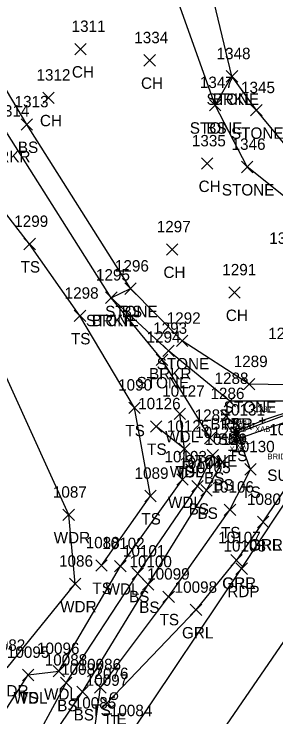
# Model space of a CAD drawing. Extents: x 1651685 to 1653558, y 889533 to 891085.
# Drawn here: x 1652635.2 to 1652681.1, y 890214.6 to 890337.8 of the extents above; entities that cross this region are included whole.
import ezdxf

# ---------------------------------------------------------------- set-up
doc = ezdxf.new("R2010")
doc.units = 0
for name, color, linetype in [('B_A', 7, 'Continuous'), ('B_C', 7, 'Continuous'), ('B_I', 7, 'Continuous'), ('B_TIC', 7, 'Continuous'), ('BSUBM', 7, 'Continuous'), ('C_A', 7, 'Continuous'), ('C_I', 7, 'Continuous'), ('CBP', 7, 'Continuous'), ('L_A', 7, 'Continuous'), ('L_I', 7, 'Continuous'), ('L_TIC', 7, 'Continuous'), ('LASF', 7, 'Continuous'), ('LAWA', 7, 'Continuous'), ('LAWE', 7, 'Continuous'), ('LELB', 7, 'Continuous'), ('P_A', 7, 'Continuous'), ('P_I', 7, 'Continuous'), ('P_TIC', 7, 'Continuous'), ('PET', 7, 'Continuous'), ('PRC', 7, 'Continuous'), ('R_A', 7, 'Continuous'), ('R_I', 7, 'Continuous'), ('R_TIC', 7, 'Continuous'), ('RGR', 7, 'Continuous'), ('U_A', 7, 'Continuous'), ('U_I', 7, 'Continuous')]:
    doc.layers.add(name, color=color, linetype=linetype)

msp = doc.modelspace()

# ---------------------------------------------------------------- linework, layer by layer
at = {"layer": 'B_TIC'}
for p, q in [((1652678.73, 890266.55), (1652678.8, 890266.55)), ((1652678.73, 890266.55), (1652678.8, 890266.55)), ((1652673.79, 890264.5), (1652673.87, 890264.5)), ((1652674.28, 890264.42), (1652674.36, 890264.42)), ((1652675.36, 890263.62), (1652675.43, 890263.62)), ((1652674.25, 890263.02), (1652674.33, 890263.02))]:
    msp.add_line(p, q, dxfattribs=at)
for points in [[(1652678.72, 890266.05), (1652678.72, 890267.05)], [(1652678.72, 890266.05), (1652678.72, 890267.05)], [(1652678.22, 890266.55), (1652679.22, 890266.55)], [(1652678.22, 890266.55), (1652679.22, 890266.55)], [(1652673.29, 890264.5), (1652674.29, 890264.5)], [(1652673.78, 890264.42), (1652674.78, 890264.42)], [(1652673.79, 890264), (1652673.79, 890265)], [(1652674.28, 890263.92), (1652674.28, 890264.92)], [(1652674.25, 890262.52), (1652674.25, 890263.52)], [(1652674.85, 890263.62), (1652675.85, 890263.62)], [(1652675.35, 890263.12), (1652675.35, 890264.12)], [(1652673.75, 890263.02), (1652674.75, 890263.02)]]:
    msp.add_lwpolyline(points, dxfattribs=at)
at = {"layer": 'BSUBM'}
for points in [[(1652674.28, 890264.42), (1652684.64, 890268.23), (1652686.91, 890265.29), (1652686.2, 890264.56), (1652684.09, 890266.74), (1652675.35, 890263.62)], [(1652707.27, 890221.55), (1652712.18, 890235.57), (1652700.43, 890249.63), (1652694.58, 890256.58), (1652684.61, 890268.45), (1652678.72, 890266.55)], [(1652674.25, 890263.02), (1652673.79, 890264.5), (1652678.72, 890266.55)]]:
    msp.add_lwpolyline(points, dxfattribs=at)
at = {"layer": 'CBP'}
for radius in [0.625, 0.0833]:
    msp.add_circle((1652652.72, 890218.25), radius, dxfattribs=at)
at = {"layer": 'L_TIC'}
for points in [[(1652645.86, 890330.63), (1652647.86, 890332.63)], [(1652647.86, 890330.63), (1652645.86, 890332.63)], [(1652657.97, 890328.65), (1652659.97, 890330.65)], [(1652659.97, 890328.65), (1652657.97, 890330.65)], [(1652672.4, 890325.85), (1652674.4, 890327.85)], [(1652674.4, 890325.85), (1652672.4, 890327.85)], [(1652672.4, 890325.85), (1652674.4, 890327.85)], [(1652674.4, 890325.85), (1652672.4, 890327.85)], [(1652672.4, 890325.85), (1652674.4, 890327.85)], [(1652674.4, 890325.85), (1652672.4, 890327.85)], [(1652640.26, 890322.1), (1652642.26, 890324.1)], [(1652642.26, 890322.1), (1652640.26, 890324.1)], [(1652669.46, 890320.8), (1652671.46, 890322.8)], [(1652671.46, 890320.8), (1652669.46, 890322.8)], [(1652669.46, 890320.8), (1652671.46, 890322.8)], [(1652671.46, 890320.8), (1652669.46, 890322.8)], [(1652676.67, 890319.9), (1652678.67, 890321.9)], [(1652678.67, 890319.9), (1652676.67, 890321.9)], [(1652636.44, 890317.42), (1652638.44, 890319.42)], [(1652638.44, 890317.42), (1652636.44, 890319.42)], [(1652668.06, 890310.58), (1652670.06, 890312.58)], [(1652670.06, 890310.58), (1652668.06, 890312.58)], [(1652675.08, 890309.97), (1652677.08, 890311.97)], [(1652677.08, 890309.97), (1652675.08, 890311.97)], [(1652636.95, 890296.47), (1652638.95, 890298.47)], [(1652638.95, 890296.47), (1652636.95, 890298.47)], [(1652661.9, 890295.52), (1652663.9, 890297.52)], [(1652663.9, 890295.52), (1652661.9, 890297.52)], [(1652654.64, 890288.65), (1652656.64, 890290.65)], [(1652656.64, 890288.65), (1652654.64, 890290.65)], [(1652654.64, 890288.65), (1652656.64, 890290.65)], [(1652656.64, 890288.65), (1652654.64, 890290.65)], [(1652654.64, 890288.65), (1652656.64, 890290.65)], [(1652656.64, 890288.65), (1652654.64, 890290.65)], [(1652651.26, 890287.07), (1652653.26, 890289.07)], [(1652653.26, 890287.07), (1652651.26, 890289.07)], [(1652651.26, 890287.07), (1652653.26, 890289.07)], [(1652653.26, 890287.07), (1652651.26, 890289.07)], [(1652672.83, 890287.98), (1652674.83, 890289.98)], [(1652674.83, 890287.98), (1652672.83, 890289.98)], [(1652645.77, 890283.89), (1652647.77, 890285.89)], [(1652647.77, 890283.89), (1652645.77, 890285.89)], [(1652663.66, 890279.5), (1652665.66, 890281.5)], [(1652665.66, 890279.5), (1652663.66, 890281.5)], [(1652661.28, 890277.74), (1652663.28, 890279.74)], [(1652663.28, 890277.74), (1652661.28, 890279.74)], [(1652660.14, 890276.18), (1652662.14, 890278.18)], [(1652662.14, 890276.18), (1652660.14, 890278.18)], [(1652675.41, 890271.91), (1652677.41, 890273.91)], [(1652677.41, 890271.91), (1652675.41, 890273.91)], [(1652672.03, 890268.95), (1652674.03, 890270.95)], [(1652674.03, 890268.95), (1652672.03, 890270.95)], [(1652672.03, 890268.95), (1652674.03, 890270.95)], [(1652674.03, 890268.95), (1652672.03, 890270.95)], [(1652655.31, 890267.79), (1652657.31, 890269.79)], [(1652657.31, 890267.79), (1652655.31, 890269.79)], [(1652663.27, 890266.72), (1652665.27, 890268.72)], [(1652665.27, 890266.72), (1652663.27, 890268.72)], [(1652671.38, 890266.3), (1652673.38, 890268.3)], [(1652673.38, 890266.3), (1652671.38, 890268.3)], [(1652659.12, 890264.52), (1652661.12, 890266.52)], [(1652661.12, 890264.52), (1652659.12, 890266.52)], [(1652668.56, 890262.49), (1652670.56, 890264.49)], [(1652670.56, 890262.49), (1652668.56, 890264.49)], [(1652673.28, 890263.42), (1652675.28, 890265.42)], [(1652675.28, 890263.42), (1652673.28, 890265.42)], [(1652664.08, 890260.58), (1652666.08, 890262.58)], [(1652666.08, 890260.58), (1652664.08, 890262.58)], [(1652664.08, 890260.58), (1652666.08, 890262.58)], [(1652666.08, 890260.58), (1652664.08, 890262.58)], [(1652669.05, 890259.48), (1652671.05, 890261.48)], [(1652671.05, 890259.48), (1652669.05, 890261.48)], [(1652670.69, 890258.27), (1652672.69, 890260.27)], [(1652672.69, 890258.27), (1652670.69, 890260.27)], [(1652675.63, 890256.99), (1652677.63, 890258.99)], [(1652677.63, 890256.99), (1652675.63, 890258.99)], [(1652663.75, 890255.22), (1652665.75, 890257.22)], [(1652665.75, 890255.22), (1652663.75, 890257.22)], [(1652666.36, 890254.05), (1652668.36, 890256.05)], [(1652668.36, 890254.05), (1652666.36, 890256.05)], [(1652667.92, 890253.32), (1652669.92, 890255.32)], [(1652669.92, 890253.32), (1652667.92, 890255.32)], [(1652658.11, 890252.33), (1652660.11, 890254.33)], [(1652660.11, 890252.33), (1652658.11, 890254.33)], [(1652643.79, 890249.03), (1652645.79, 890251.03)], [(1652645.79, 890249.03), (1652643.79, 890251.03)], [(1652672.05, 890249.91), (1652674.05, 890251.91)], [(1652674.05, 890249.91), (1652672.05, 890251.91)], [(1652649.54, 890240.16), (1652651.54, 890242.16)], [(1652651.54, 890240.16), (1652649.54, 890242.16)], [(1652652.84, 890240.02), (1652654.84, 890242.02)], [(1652654.84, 890240.02), (1652652.84, 890242.02)], [(1652655.91, 890238.72), (1652657.91, 890240.72)], [(1652657.91, 890238.72), (1652655.91, 890240.72)], [(1652644.93, 890236.94), (1652646.93, 890238.94)], [(1652646.93, 890236.94), (1652644.93, 890238.94)], [(1652657.7, 890236.83), (1652659.7, 890238.83)], [(1652659.7, 890236.83), (1652657.7, 890238.83)], [(1652661.3, 890234.67), (1652663.3, 890236.67)], [(1652663.3, 890234.67), (1652661.3, 890236.67)], [(1652636.71, 890220.97), (1652638.71, 890222.97)], [(1652638.71, 890220.97), (1652636.71, 890222.97)], [(1652636.71, 890220.97), (1652638.71, 890222.97)], [(1652638.71, 890220.97), (1652636.71, 890222.97)], [(1652642.05, 890221.64), (1652644.05, 890223.64)], [(1652644.05, 890221.64), (1652642.05, 890223.64)], [(1652643.34, 890219.61), (1652645.34, 890221.61)], [(1652645.34, 890219.61), (1652643.34, 890221.61)], [(1652646.21, 890218), (1652648.21, 890220)], [(1652648.21, 890218), (1652646.21, 890220)], [(1652649.34, 890218.8), (1652651.34, 890220.8)], [(1652651.34, 890218.8), (1652649.34, 890220.8)]]:
    msp.add_lwpolyline(points, dxfattribs=at)
at = {"layer": 'LASF'}
for points in [[(1652702.4, 890272.51), (1652693.12, 890283.15), (1652692.05, 890298.23), (1652676.08, 890310.97), (1652670.46, 890321.8), (1652673.4, 890326.85)], [(1652702.77, 890302.09), (1652702.08, 890309.18), (1652696.3, 890309.13), (1652689.69, 890306.45), (1652677.67, 890320.9), (1652673.4, 890326.85)], [(1652669.56, 890263.49), (1652661.14, 890277.18), (1652652.26, 890288.07), (1652655.64, 890289.65)], [(1652698.14, 890254.71), (1652698.94, 890261.96), (1652686.33, 890272.72), (1652676.41, 890272.91), (1652664.66, 890280.5), (1652655.64, 890289.65)]]:
    msp.add_lwpolyline(points, dxfattribs=at)
at = {"layer": 'LAWA'}
for points in [[(1652634, 890223.2), (1652645.93, 890237.94), (1652644.79, 890250.03), (1652631.58, 890279.12), (1652627.58, 890295.01), (1652615.37, 890319.79), (1652592.1, 890369.11), (1652560.95, 890333.56)], [(1652637.71, 890221.97), (1652643.05, 890222.64), (1652653.84, 890241.02), (1652664.75, 890256.22), (1652665.08, 890261.58), (1652664.27, 890267.72)]]:
    msp.add_lwpolyline(points, dxfattribs=at)
at = {"layer": 'LAWE'}
for points in [[(1652673.4, 890326.85), (1652668.24, 890348.37), (1652662.56, 890365.27), (1652663.6, 890385.9), (1652673.62, 890404.58), (1652681.39, 890424.61)], [(1652673.03, 890269.95), (1652662.28, 890278.74), (1652652.26, 890288.07), (1652634.07, 890316.8), (1652621.98, 890338.92), (1652608.93, 890362.26), (1652605.24, 890386.79), (1652601.16, 890393.28)]]:
    msp.add_lwpolyline(points, dxfattribs=at)
at = {"layer": 'LELB'}
for points in [[(1652670.46, 890321.8), (1652661.19, 890347.87), (1652659.49, 890365.61), (1652660.32, 890386.85), (1652664.7, 890405.27)], [(1652650.54, 890241.16), (1652659.11, 890253.33), (1652656.31, 890268.79), (1652646.77, 890284.89), (1652637.95, 890297.47), (1652620.82, 890319.5), (1652601.11, 890367.7), (1652597.25, 890382.58), (1652593.27, 890396.32)], [(1652655.64, 890289.65), (1652637.44, 890318.42), (1652625.19, 890339.02), (1652613.75, 890361.43), (1652608, 890385.77), (1652605.05, 890393.3)], [(1652696.63, 890256.86), (1652685.4, 890269.93), (1652673.03, 890269.95)], [(1652293.22, 889915.66), (1652303.09, 889907.93), (1652317.35, 889908.79), (1652320.69, 889910.3), (1652331.92, 889916.22), (1652367.25, 889934.93), (1652401.81, 889955.3), (1652430.74, 889974.75), (1652457.46, 889995.31), (1652485.92, 890020.39), (1652507.16, 890038.54), (1652516.29, 890046.9), (1652543.45, 890076.69), (1652569.75, 890105.32), (1652598.99, 890142.55), (1652623.84, 890175.33), (1652642.78, 890202.62), (1652649.43, 890213.08), (1652650.34, 890219.8), (1652662.3, 890235.67), (1652673.05, 890250.91), (1652676.63, 890257.99), (1652674.28, 890264.42)], [(1652665.08, 890261.58), (1652660.12, 890265.52)], [(1652541.97, 890077.83), (1652566.6, 890107.88), (1652595.78, 890145.78), (1652618.66, 890179.03), (1652637.28, 890207.53), (1652644.34, 890220.61), (1652656.91, 890239.72), (1652667.36, 890255.05), (1652670.05, 890260.48)], [(1652348.15, 889927.34), (1652366.56, 889935.99), (1652400.4, 889956.7), (1652430.05, 889976.64), (1652456.7, 889996.32), (1652485.07, 890021.64), (1652505.87, 890039.82), (1652515.19, 890048.17), (1652541.97, 890077.83), (1652568.76, 890106.07), (1652597.37, 890144.26), (1652620.77, 890177.54), (1652638.78, 890206.49), (1652647.21, 890219), (1652658.7, 890237.83), (1652668.92, 890254.32), (1652671.69, 890259.27)], [(1652442.28, 889988.62), (1652454.4, 889999.19), (1652483.45, 890024.67), (1652494.27, 890035.14), (1652511.88, 890052.95), (1652537.3, 890082.09), (1652561.99, 890110.81), (1652590.74, 890149.47), (1652610.85, 890183.15), (1652631.18, 890211.95), (1652637.71, 890221.97)]]:
    msp.add_lwpolyline(points, dxfattribs=at)
at = {"layer": 'P_TIC'}
for points in [[(1652674.09, 890239.6), (1652676.09, 890241.6)], [(1652676.09, 890239.6), (1652674.09, 890241.6)]]:
    msp.add_lwpolyline(points, dxfattribs=at)
at = {"layer": 'PET'}
msp.add_lwpolyline([(1652333.65, 889912.67), (1652369.12, 889931.53), (1652403.15, 889952.41), (1652433.06, 889972.26), (1652459.32, 889992.68), (1652488.38, 890016.94), (1652517.96, 890045.24), (1652545.96, 890074.03), (1652572.08, 890103.38), (1652602.1, 890139.63), (1652627.16, 890172.83), (1652646.68, 890199.42), (1652655.75, 890211.75), (1652675.09, 890240.6), (1652688.17, 890260.37)], dxfattribs=at)
at = {"layer": 'PRC'}
msp.add_lwpolyline([(1652339.13, 889902.36), (1652374.76, 889921.45), (1652409.7, 889942.76), (1652439.67, 889962.96), (1652466.37, 889983.16), (1652495.64, 890007.9), (1652525.65, 890036.36), (1652554.01, 890065.88), (1652580.92, 890096.26), (1652611.45, 890132.24), (1652636.96, 890165.09), (1652656.96, 890191.59), (1652665.11, 890202.52), (1652686.51, 890233.67), (1652697.14, 890249.86)], dxfattribs=at)
at = {"layer": 'R_TIC'}
for points in [[(1652677.88, 890247.77), (1652679.88, 890249.77)], [(1652679.88, 890247.77), (1652677.88, 890249.77)], [(1652677.88, 890247.77), (1652679.88, 890249.77)], [(1652679.88, 890247.77), (1652677.88, 890249.77)], [(1652673.18, 890241.06), (1652675.18, 890243.06)], [(1652675.18, 890241.06), (1652673.18, 890243.06)], [(1652673.18, 890241.06), (1652675.18, 890243.06)], [(1652675.18, 890241.06), (1652673.18, 890243.06)], [(1652666.1, 890232.37), (1652668.1, 890234.37)], [(1652668.1, 890232.37), (1652666.1, 890234.37)], [(1652650.52, 890216.07), (1652652.52, 890218.07)], [(1652652.52, 890216.07), (1652650.52, 890218.07)]]:
    msp.add_lwpolyline(points, dxfattribs=at)
at = {"layer": 'RGR'}
for points in [[(1652678.88, 890248.77), (1652686.53, 890260.18)], [(1652678.88, 890248.77), (1652674.18, 890242.06)], [(1652651.52, 890217.07), (1652667.1, 890233.37), (1652674.18, 890242.06)]]:
    msp.add_lwpolyline(points, dxfattribs=at)

# ---------------------------------------------------------------- texts
at = {"layer": 'B_A'}
for s, p in [('XAB', (1652677.44, 890264.55)), ('XAB', (1652677.44, 890264.55)), ('XAB', (1652672.51, 890262.5)), ('XAT', (1652672.98, 890262.42)), ('XAB', (1652672.97, 890261.02)), ('XAT', (1652674.06, 890261.62))]:
    msp.add_text(s, height=1, dxfattribs=at).set_placement(p)
at = {"layer": 'B_C'}
msp.add_text('BRIDGE SEAT DEPTH 1.65', height=1, dxfattribs=at).set_placement((1652679.62, 890259.75))
at = {"layer": 'B_I'}
for s, p in [('1287', (1652677.38, 890268.05)), ('1287', (1652677.38, 890268.05)), ('1284', (1652672.44, 890266)), ('10131', (1652673.01, 890265.92)), ('10137', (1652673.8, 890265.12)), ('1283', (1652672.9, 890264.52))]:
    msp.add_text(s, height=1, dxfattribs=at).set_placement(p)
at = {"layer": 'C_A'}
msp.add_text('TIE', height=2, dxfattribs=at).set_placement((1652650.8, 890213.25))
at = {"layer": 'C_I'}
msp.add_text('2076', height=2, dxfattribs=at).set_placement((1652649.32, 890221.25))
at = {"layer": 'L_A'}
for s, p in [('CH', (1652645.35, 890326.63)), ('CH', (1652657.46, 890324.65)), ('STONE', (1652668.94, 890321.85)), ('STONE', (1652668.94, 890321.85)), ('BRKL', (1652670.04, 890321.85)), ('CH', (1652639.75, 890318.1)), ('STONE', (1652666.01, 890316.8)), ('BS', (1652668.9, 890316.8)), ('STONE', (1652673.22, 890315.9)), ('BS', (1652635.88, 890313.42)), ('BRKR', (1652630.66, 890311.8)), ('CH', (1652667.55, 890306.58)), ('STONE', (1652671.62, 890305.97)), ('TS', (1652636.36, 890292.47)), ('CH', (1652661.39, 890291.52)), ('STONE', (1652651.18, 890284.65)), ('STONE', (1652651.18, 890284.65)), ('BS', (1652654.08, 890284.65)), ('CH', (1652672.32, 890283.98)), ('STONE', (1652647.81, 890283.07)), ('BRKR', (1652648.85, 890283.07)), ('TS', (1652645.18, 890279.89)), ('STONE', (1652660.2, 890275.5)), ('BRKR', (1652658.87, 890273.74)), ('STONE', (1652656.68, 890272.18)), ('STONE', (1652671.95, 890267.91)), ('BRKR', (1652669.62, 890264.95)), ('TS', (1652671.44, 890264.95)), ('TS', (1652654.72, 890263.79)), ('WDL', (1652661.69, 890262.72)), ('SH', (1652670.87, 890262.3)), ('TS', (1652658.53, 890260.52)), ('TS', (1652672.69, 890259.42)), ('STONE', (1652665.1, 890258.49)), ('WDL', (1652662.5, 890256.58)), ('TS', (1652663.49, 890256.58)), ('BS', (1652668.49, 890255.48)), ('BS', (1652670.13, 890254.27)), ('TS', (1652675.04, 890252.99)), ('WDL', (1652662.17, 890251.22)), ('BS', (1652665.81, 890250.05)), ('BS', (1652667.36, 890249.32)), ('TS', (1652657.52, 890248.33)), ('TS', (1652671.46, 890245.91)), ('WDR', (1652642.16, 890245.03)), ('TS', (1652648.95, 890236.16)), ('WDL', (1652651.26, 890236.02)), ('BS', (1652655.36, 890234.72)), ('WDR', (1652643.29, 890232.94)), ('BS', (1652657.14, 890232.83)), ('TS', (1652660.71, 890230.67)), ('WDR', (1652631.36, 890218.2)), ('WDL', (1652635.13, 890216.97)), ('TS', (1652636.12, 890216.97)), ('WDL', (1652640.47, 890217.64)), ('BS', (1652642.78, 890215.61)), ('TS', (1652648.75, 890214.8)), ('BS', (1652645.65, 890214))]:
    msp.add_text(s, height=2, dxfattribs=at).set_placement(p)
at = {"layer": 'L_I'}
for s, p in [('1311', (1652645.3, 890334.63)), ('1334', (1652656.28, 890332.65)), ('1348', (1652670.7, 890329.85)), ('1348', (1652670.7, 890329.85)), ('1348', (1652670.7, 890329.85)), ('1312', (1652639.14, 890326.1)), ('1347', (1652667.77, 890324.8)), ('1347', (1652667.77, 890324.8)), ('1345', (1652674.98, 890323.9)), ('1313', (1652635.31, 890321.42)), ('1314', (1652631.95, 890319.8)), ('1335', (1652666.37, 890314.58)), ('1346', (1652673.33, 890313.97)), ('1299', (1652635.25, 890300.47)), ('1297', (1652660.21, 890299.52)), ('1336', (1652679.94, 890297.5)), ('1296', (1652652.89, 890292.65)), ('1296', (1652652.89, 890292.65)), ('1296', (1652652.89, 890292.65)), ('1291', (1652671.7, 890291.98)), ('1295', (1652649.57, 890291.07)), ('1295', (1652649.57, 890291.07)), ('1298', (1652644.08, 890287.89)), ('1292', (1652661.96, 890283.5)), ('1293', (1652659.59, 890281.74)), ('1290', (1652679.75, 890280.81)), ('1294', (1652658.44, 890280.18)), ('1289', (1652673.7, 890275.91)), ('1288', (1652670.34, 890272.95)), ('1288', (1652670.34, 890272.95)), ('1090', (1652653.45, 890271.79)), ('10127', (1652661.17, 890270.72)), ('1286', (1652669.63, 890270.3)), ('10126', (1652656.96, 890268.52)), ('10131', (1652671.74, 890267.42)), ('1285', (1652666.86, 890266.49)), ('10125', (1652661.98, 890264.58)), ('10125', (1652661.98, 890264.58)), ('10128', (1652666.95, 890263.48)), ('10129', (1652668.58, 890262.27)), ('10130', (1652673.44, 890260.99)), ('10103', (1652661.57, 890259.22)), ('10104', (1652664.18, 890258.05)), ('1089', (1652656.33, 890256.33)), ('10105', (1652665.73, 890257.32)), ('10106', (1652669.81, 890253.91)), ('1087', (1652642.02, 890253.03)), ('1088', (1652647.77, 890244.16)), ('10102', (1652650.66, 890244.02)), ('10101', (1652654.3, 890242.72)), ('1086', (1652643.1, 890240.94)), ('10100', (1652655.43, 890240.83)), ('10099', (1652658.54, 890238.67)), ('1082', (1652631.23, 890226.2)), ('10096', (1652639.24, 890225.64)), ('10095', (1652633.96, 890224.97)), ('10095', (1652633.96, 890224.97)), ('10088', (1652640.59, 890223.61)), ('10087', (1652643.46, 890222)), ('10086', (1652646.53, 890222.8)), ('10085', (1652645.68, 890216.08))]:
    msp.add_text(s, height=2, dxfattribs=at).set_placement(p)
at = {"layer": 'P_A'}
msp.add_text('RDP', height=2, dxfattribs=at).set_placement((1652672.58, 890235.6))
at = {"layer": 'P_I'}
for s, p in [('10108', (1652671.91, 890243.6)), ('10084', (1652652, 890214.75))]:
    msp.add_text(s, height=2, dxfattribs=at).set_placement(p)
at = {"layer": 'R_A'}
for s, p in [('GRR', (1652676.37, 890243.77)), ('GRL', (1652676.43, 890243.77)), ('GRR', (1652671.67, 890237.06)), ('GRL', (1652671.73, 890237.06)), ('GRL', (1652664.64, 890228.37))]:
    msp.add_text(s, height=2, dxfattribs=at).set_placement(p)
at = {"layer": 'R_I'}
for s, p in [('1080', (1652676.03, 890251.77)), ('1080', (1652676.03, 890251.77)), ('10107', (1652671, 890245.06)), ('10107', (1652671, 890245.06)), ('10098', (1652663.35, 890236.37)), ('10097', (1652647.77, 890220.07))]:
    msp.add_text(s, height=2, dxfattribs=at).set_placement(p)
at = {"layer": 'U_A'}
msp.add_text('SUBS', height=2, dxfattribs=at).set_placement((1652679.58, 890255.96))
at = {"layer": 'U_I'}
msp.add_text('10135', height=2, dxfattribs=at).set_placement((1652679.94, 890263.96))

doc.saveas('drawing.dxf')
